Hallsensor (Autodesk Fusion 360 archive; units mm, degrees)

design "Hallsensor"
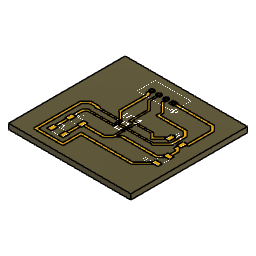
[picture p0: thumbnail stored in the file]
sketch "Outline" plane through (0, 0, 0) normal (0, 0, 1) x axis (1, 0, 0)
  line L1 (34.27, 6.35) -> (0, 6.35)
  line L2 (34.27, 39.04) -> (34.27, 6.35)
  line L3 (0, 39.04) -> (34.27, 39.04)
  line L4 (0, 6.35) -> (0, 39.04)
canvas "Canvas1" bodies "Board"
canvas "Canvas2" bodies "Board"
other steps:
extrude "Extrude1" sketch "Outline" blind 1.5 bodies "Board"
pcbextrude "PCBExtrude1"
pcbextrude "PCBExtrude1"
pcbextrude "PCBExtrude1"
pcbextrude "PCBExtrude2" bodies "CopperHoles"
create_component "CreateComponent1"
create_component "CreateComponent2"
create_component "CreateComponent3"
create_component "CreateComponent4"
as_built_joint "As-built1"
named bodies: "Board", "CopperHoles"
